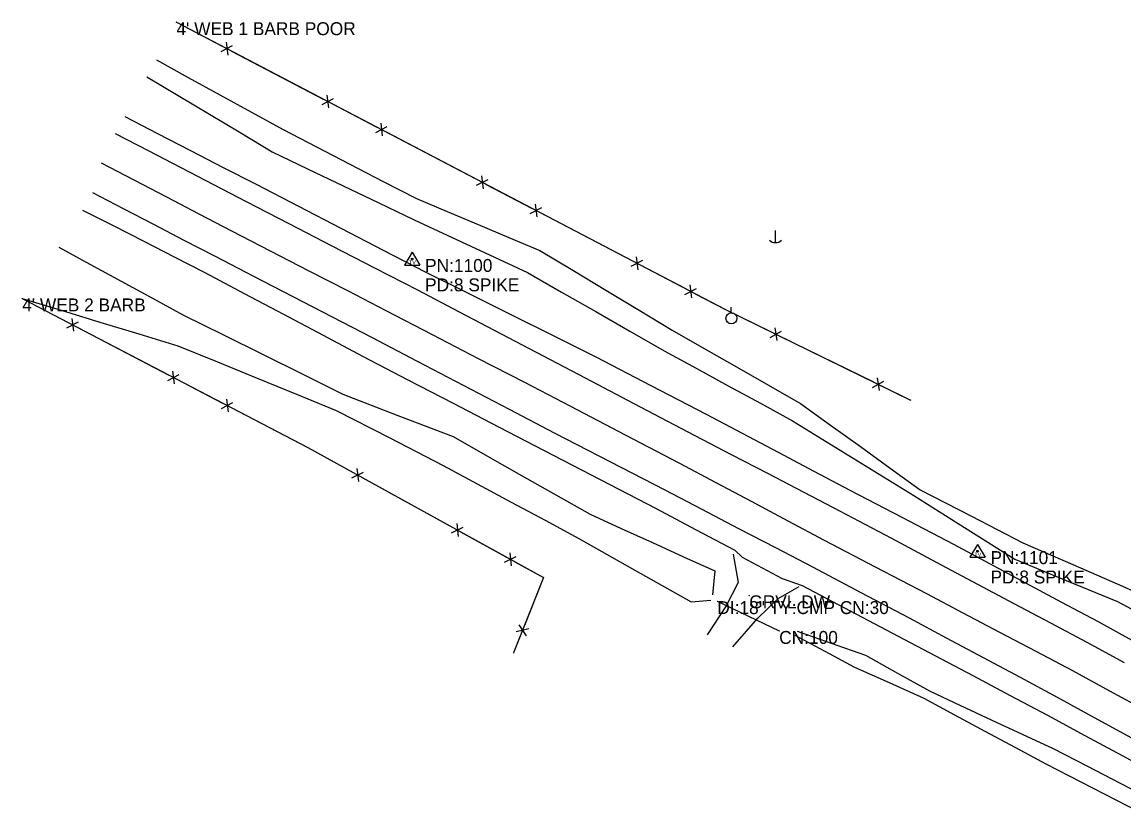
# Model space of a CAD drawing. Extents: x 1193883 to 1197064, y 1474583 to 1477379.
# Drawn here: x 1193883 to 1194308.8, y 1477071.5 to 1477379.2 of the extents above; entities that cross this region are included whole.
import ezdxf

# ---------------------------------------------------------------- set-up
doc = ezdxf.new("R2010")
doc.units = 0
for name, color, linetype in [('S_DITCHLINE', 7, 'Continuous'), ('S_DRG_PT_SYM', 7, 'Continuous'), ('S_DRIVEWAY', 7, 'Continuous'), ('S_EDGE_PAVEMENT', 7, 'Continuous'), ('S_FENCE', 7, 'Continuous'), ('S_FENCE_ANNOT', 7, 'Continuous'), ('S_MSC_PT_SYM', 7, 'Continuous'), ('S_PAVEMENT_CROWN', 7, 'Continuous'), ('S_SECONDARY_CTL', 7, 'Continuous'), ('S_SECONDARY_CTL_ANNOT', 7, 'Continuous'), ('S_SHOULDER', 7, 'Continuous'), ('S_SIDE_DRAIN', 7, 'Continuous'), ('S_SIDE_DRAIN_ANNOT', 7, 'Continuous'), ('S_SURVEY_TEXT_ANNOT', 7, 'Continuous'), ('S_UTILITY_POLE', 7, 'Continuous')]:
    doc.layers.add(name, color=color, linetype=linetype)

msp = doc.modelspace()

# ---------------------------------------------------------------- linework, layer by layer
at = {"layer": 'S_DITCHLINE'}
for points in [[(1193934.94, 1477364.5), (1193947.19, 1477357.77), (1193959.44, 1477351.04), (1193971.69, 1477344.3), (1193983.94, 1477337.57), (1193996.8, 1477330.9), (1194009.66, 1477324.23), (1194022.52, 1477317.56), (1194035.38, 1477310.89), (1194047.29, 1477305.89), (1194059.19, 1477300.89), (1194071.1, 1477295.89), (1194083.01, 1477290.89), (1194095.81, 1477283.18), (1194108.61, 1477275.46), (1194121.41, 1477267.75), (1194134.21, 1477260.03), (1194146.62, 1477252.94), (1194159.02, 1477245.84), (1194171.43, 1477238.75), (1194183.84, 1477231.66), (1194195.38, 1477223.33), (1194206.93, 1477215.01), (1194218.47, 1477206.69), (1194230.01, 1477198.36), (1194249.87, 1477188.1), (1194269.73, 1477177.84), (1194288.97, 1477169.49), (1194308.2, 1477161.14), (1194323.51, 1477154.1)], [(1193931.19, 1477357.98), (1193943.29, 1477350.74), (1193955.4, 1477343.5), (1193967.5, 1477336.26), (1193979.61, 1477329.03), (1193993.34, 1477322.44), (1194007.08, 1477315.86), (1194020.82, 1477309.28), (1194034.56, 1477302.69), (1194056.42, 1477292.52), (1194078.29, 1477282.34), (1194091.49, 1477274.78), (1194104.68, 1477267.21), (1194117.88, 1477259.65), (1194131.08, 1477252.08), (1194143.48, 1477245.32), (1194155.87, 1477238.55), (1194168.27, 1477231.79), (1194180.67, 1477225.03), (1194192.41, 1477217.8), (1194204.15, 1477210.58), (1194215.88, 1477203.35), (1194227.62, 1477196.13), (1194247.11, 1477183.81), (1194266.6, 1477171.49), (1194286.46, 1477163.33), (1194306.32, 1477155.18), (1194320.76, 1477147.45)], [(1193897.17, 1477292.11), (1193909.22, 1477285.56), (1193921.28, 1477279), (1193933.34, 1477272.44), (1193945.39, 1477265.88), (1193960.77, 1477258.25), (1193976.15, 1477250.61), (1193991.53, 1477242.98), (1194006.91, 1477235.34), (1194028.24, 1477227.11), (1194049.56, 1477218.87), (1194062.79, 1477211.37), (1194076.01, 1477203.88), (1194089.24, 1477196.38), (1194102.46, 1477188.89), (1194114.52, 1477183.41), (1194126.57, 1477177.94), (1194138.62, 1477172.46), (1194150.67, 1477166.99), (1194149.79, 1477157.71)], [(1193882.99, 1477272.33), (1193898.05, 1477267.75), (1193913.11, 1477263.18), (1193928.17, 1477258.6), (1193943.24, 1477254.02), (1193958.52, 1477247.77), (1193973.81, 1477241.52), (1193989.1, 1477235.27), (1194004.39, 1477229.03), (1194025.07, 1477218.36), (1194045.75, 1477207.7), (1194058.86, 1477200.64), (1194071.97, 1477193.59), (1194085.08, 1477186.54), (1194098.19, 1477179.49), (1194119.83, 1477167.26), (1194141.48, 1477155.03), (1194149.17, 1477155.65)], [(1194181.57, 1477142.09), (1194193.14, 1477135.96), (1194204.71, 1477129.83), (1194218.09, 1477123.79), (1194231.46, 1477117.74), (1194243.25, 1477111.4), (1194255.04, 1477105.06), (1194266.83, 1477098.71), (1194278.62, 1477092.37), (1194292.11, 1477085.41), (1194305.6, 1477078.44), (1194319.09, 1477071.47)], [(1194182.44, 1477143.74), (1194195.66, 1477139.09), (1194208.88, 1477134.44), (1194221.24, 1477127.51), (1194233.61, 1477120.58), (1194245.56, 1477115.01), (1194257.51, 1477109.43), (1194269.46, 1477103.86), (1194281.41, 1477098.29), (1194294.37, 1477091.61), (1194307.32, 1477084.93), (1194320.28, 1477078.25)]]:
    msp.add_lwpolyline(points, dxfattribs=at)
at = {"layer": 'S_DRG_PT_SYM'}
for points in [[(1194151.64, 1477155.29), (1194151.64, 1477155.34), (1194151.64, 1477155.29), (1194151.59, 1477155.29), (1194151.64, 1477155.29), (1194151.64, 1477155.24), (1194151.64, 1477155.29), (1194151.69, 1477155.29)], [(1194175.55, 1477143.76), (1194175.55, 1477143.81), (1194175.55, 1477143.76), (1194175.5, 1477143.76), (1194175.55, 1477143.76), (1194175.55, 1477143.71), (1194175.55, 1477143.76), (1194175.6, 1477143.76)]]:
    msp.add_lwpolyline(points, dxfattribs=at)
at = {"layer": 'S_DRIVEWAY'}
for points in [[(1194157.73, 1477173.42), (1194159.73, 1477162.49), (1194155.1, 1477153.51), (1194147.71, 1477142.28)], [(1194157.61, 1477137.66), (1194167.36, 1477148.7), (1194175.15, 1477156.3), (1194183.29, 1477160.93)]]:
    msp.add_lwpolyline(points, dxfattribs=at)
at = {"layer": 'S_EDGE_PAVEMENT'}
for points in [[(1193919.03, 1477336.12), (1193931.66, 1477329.53), (1193944.29, 1477322.94), (1193956.92, 1477316.35), (1193969.55, 1477309.77), (1193986.1, 1477301.24), (1194002.65, 1477292.7), (1194019.19, 1477284.17), (1194035.74, 1477275.64), (1194051.95, 1477267.13), (1194068.17, 1477258.62), (1194084.38, 1477250.11), (1194100.59, 1477241.6), (1194121.79, 1477230.46), (1194142.99, 1477219.33), (1194157.03, 1477212.03), (1194171.08, 1477204.73), (1194185.13, 1477197.43), (1194199.17, 1477190.13), (1194218.65, 1477179.7), (1194238.13, 1477169.27), (1194252.2, 1477161.83), (1194266.27, 1477154.38), (1194280.35, 1477146.93), (1194294.42, 1477139.49), (1194308.91, 1477131.54)], [(1193910.25, 1477313.24), (1193922.01, 1477307.12), (1193933.77, 1477301), (1193945.54, 1477294.88), (1193957.3, 1477288.76), (1193972.47, 1477280.89), (1193987.64, 1477273.02), (1194002.82, 1477265.15), (1194017.99, 1477257.28), (1194035.72, 1477248.01), (1194053.45, 1477238.75), (1194071.18, 1477229.48), (1194088.91, 1477220.21), (1194110.14, 1477209.24), (1194131.37, 1477198.26), (1194145.63, 1477190.84), (1194159.89, 1477183.42), (1194174.15, 1477176), (1194188.42, 1477168.58), (1194207.1, 1477158.69), (1194225.78, 1477148.79), (1194240.06, 1477141.15), (1194254.34, 1477133.51), (1194268.62, 1477125.87), (1194282.9, 1477118.23), (1194297.29, 1477110.37), (1194311.68, 1477102.51)]]:
    msp.add_lwpolyline(points, dxfattribs=at)
at = {"layer": 'S_FENCE'}
for p, q in [((1193942.65, 1477379.08), (1194154.51, 1477268.14)), ((1193959.92, 1477367.72), (1193964.36, 1477370.02)), ((1193961.82, 1477371.35), (1193962.46, 1477366.39)), ((1194000.8, 1477350.94), (1194001.44, 1477345.98)), ((1193998.9, 1477347.31), (1194003.34, 1477349.61)), ((1194019.66, 1477336.44), (1194024.1, 1477338.74)), ((1194021.56, 1477340.07), (1194022.2, 1477335.11)), ((1194058.63, 1477316.03), (1194063.07, 1477318.33)), ((1194060.53, 1477319.66), (1194061.17, 1477314.7)), ((1194081.29, 1477308.79), (1194081.93, 1477303.83)), ((1194079.39, 1477305.16), (1194083.83, 1477307.46)), ((1194118.37, 1477284.75), (1194122.81, 1477287.05)), ((1194120.27, 1477288.38), (1194120.91, 1477283.42)), ((1194139.13, 1477273.88), (1194143.57, 1477276.18)), ((1194141.03, 1477277.51), (1194141.67, 1477272.55)), ((1193883.04, 1477272.3), (1193993.41, 1477214.63)), ((1194154.51, 1477268.14), (1194226.25, 1477233.04)), ((1193900.31, 1477260.97), (1193904.74, 1477263.27)), ((1193902.2, 1477264.6), (1193902.85, 1477259.64)), ((1194172.09, 1477257.26), (1194176.46, 1477259.68)), ((1194173.89, 1477260.94), (1194174.66, 1477256)), ((1193941.18, 1477244.23), (1193941.82, 1477239.28)), ((1193939.28, 1477240.6), (1193943.72, 1477242.91)), ((1194211.61, 1477237.92), (1194215.98, 1477240.34)), ((1194213.41, 1477241.6), (1194214.18, 1477236.66)), ((1193960.03, 1477229.76), (1193964.47, 1477232.06)), ((1193961.93, 1477233.39), (1193962.57, 1477228.43)), ((1193993.41, 1477214.63), (1194084.44, 1477164.44)), ((1194012.4, 1477206.5), (1194012.94, 1477201.53)), ((1194010.42, 1477202.91), (1194014.91, 1477205.11)), ((1194050.93, 1477185.26), (1194051.46, 1477180.28)), ((1194048.95, 1477181.67), (1194053.44, 1477183.87)), ((1194069.47, 1477170.36), (1194073.96, 1477172.56)), ((1194071.45, 1477173.94), (1194071.98, 1477168.97)), ((1194084.44, 1477164.44), (1194072.91, 1477135.31)), ((1194078.78, 1477144.59), (1194073.92, 1477143.44)), ((1194074.97, 1477146.1), (1194077.73, 1477141.93))]:
    msp.add_line(p, q, dxfattribs=at)
for points in [[(1193942.65, 1477379.08), (1193960.37, 1477369.8)], [(1193963.91, 1477367.94), (1193999.34, 1477349.39)], [(1194002.39, 1477347.8), (1194020.1, 1477338.52)], [(1194023.65, 1477336.66), (1194059.08, 1477318.11)], [(1194062.12, 1477316.52), (1194079.84, 1477307.24)], [(1194083.39, 1477305.38), (1194118.82, 1477286.83)], [(1194121.86, 1477285.23), (1194139.58, 1477275.96)], [(1194143.12, 1477274.1), (1194154.51, 1477268.14)], [(1193883.04, 1477272.3), (1193900.75, 1477263.04)], [(1194154.51, 1477268.14), (1194172.48, 1477259.35)], [(1193904.3, 1477261.19), (1193939.73, 1477242.68)], [(1194176.07, 1477257.59), (1194212, 1477240.01)], [(1193942.77, 1477241.09), (1193960.48, 1477231.84)], [(1194215.08, 1477238.5), (1194226.25, 1477233.04)], [(1193964.02, 1477229.98), (1193993.41, 1477214.63)], [(1193993.41, 1477214.63), (1194010.92, 1477204.98)], [(1194014.42, 1477203.05), (1194049.44, 1477183.74)], [(1194052.45, 1477182.08), (1194069.96, 1477172.42)], [(1194073.46, 1477170.49), (1194084.44, 1477164.44)], [(1194084.44, 1477164.44), (1194077.09, 1477145.87)], [(1194075.62, 1477142.16), (1194072.91, 1477135.31)]]:
    msp.add_lwpolyline(points, dxfattribs=at)
at = {"layer": 'S_MSC_PT_SYM'}
for points in [[(1193942.65, 1477379.08), (1193942.65, 1477379.13), (1193942.65, 1477379.08), (1193942.6, 1477379.08), (1193942.65, 1477379.08), (1193942.65, 1477379.03), (1193942.65, 1477379.08), (1193942.7, 1477379.08)], [(1193883.04, 1477272.3), (1193883.04, 1477272.35), (1193883.04, 1477272.3), (1193882.99, 1477272.3), (1193883.04, 1477272.3), (1193883.04, 1477272.25), (1193883.04, 1477272.3), (1193883.09, 1477272.3)], [(1194154.51, 1477268.14), (1194154.51, 1477268.19), (1194154.51, 1477268.14), (1194154.46, 1477268.14), (1194154.51, 1477268.14), (1194154.51, 1477268.09), (1194154.51, 1477268.14), (1194154.56, 1477268.14)], [(1194226.25, 1477233.04), (1194226.25, 1477233.09), (1194226.25, 1477233.04), (1194226.2, 1477233.04), (1194226.25, 1477233.04), (1194226.25, 1477232.99), (1194226.25, 1477233.04), (1194226.3, 1477233.04)], [(1193993.41, 1477214.63), (1193993.41, 1477214.68), (1193993.41, 1477214.63), (1193993.36, 1477214.63), (1193993.41, 1477214.63), (1193993.41, 1477214.58), (1193993.41, 1477214.63), (1193993.46, 1477214.63)], [(1194084.44, 1477164.44), (1194084.44, 1477164.49), (1194084.44, 1477164.44), (1194084.39, 1477164.44), (1194084.44, 1477164.44), (1194084.44, 1477164.39), (1194084.44, 1477164.44), (1194084.49, 1477164.44)], [(1194164, 1477157.53), (1194164, 1477157.58), (1194164, 1477157.53), (1194163.95, 1477157.53), (1194164, 1477157.53), (1194164, 1477157.48), (1194164, 1477157.53), (1194164.05, 1477157.53)], [(1194072.91, 1477135.31), (1194072.91, 1477135.36), (1194072.91, 1477135.31), (1194072.86, 1477135.31), (1194072.91, 1477135.31), (1194072.91, 1477135.26), (1194072.91, 1477135.31), (1194072.96, 1477135.31)]]:
    msp.add_lwpolyline(points, dxfattribs=at)
at = {"layer": 'S_PAVEMENT_CROWN'}
msp.add_lwpolyline([(1193913.56, 1477324.73), (1193926.16, 1477318.15), (1193938.76, 1477311.57), (1193951.36, 1477304.99), (1193963.96, 1477298.41), (1193978.87, 1477290.72), (1193993.79, 1477283.03), (1194008.7, 1477275.34), (1194023.61, 1477267.65), (1194041.44, 1477258.4), (1194059.27, 1477249.15), (1194077.1, 1477239.91), (1194094.93, 1477230.66), (1194116, 1477219.63), (1194137.07, 1477208.6), (1194151.02, 1477201.17), (1194164.98, 1477193.75), (1194178.93, 1477186.32), (1194192.88, 1477178.9), (1194212.66, 1477168.57), (1194232.43, 1477158.24), (1194246.54, 1477150.8), (1194260.65, 1477143.35), (1194274.75, 1477135.91), (1194288.86, 1477128.46), (1194303.2, 1477120.65), (1194317.53, 1477112.84)], dxfattribs=at)
at = {"layer": 'S_SECONDARY_CTL'}
for p, q in [((1194033.72, 1477290.16), (1194030.71, 1477285.21)), ((1194033.72, 1477290.16), (1194036.66, 1477285.21)), ((1194030.71, 1477285.21), (1194036.66, 1477285.21)), ((1194252.2, 1477177.22), (1194249.19, 1477172.26)), ((1194252.2, 1477177.22), (1194255.14, 1477172.26)), ((1194249.19, 1477172.26), (1194255.14, 1477172.26))]:
    msp.add_line(p, q, dxfattribs=at)
for centre, radius in [((1194033.72, 1477287.55), 0.311), ((1194033.72, 1477287.55), 0.183), ((1194033.72, 1477287.55), 0.103), ((1194252.2, 1477174.61), 0.311), ((1194252.2, 1477174.61), 0.183), ((1194252.2, 1477174.61), 0.103)]:
    msp.add_circle(centre, radius, dxfattribs=at)
at = {"layer": 'S_SHOULDER'}
for points in [[(1193922.67, 1477342.57), (1193935.35, 1477336.03), (1193948.03, 1477329.5), (1193960.72, 1477322.96), (1193973.4, 1477316.42), (1193989.78, 1477307.94), (1194006.17, 1477299.47), (1194022.56, 1477290.99), (1194038.95, 1477282.52), (1194055.37, 1477274.34), (1194071.8, 1477266.15), (1194088.23, 1477257.97), (1194104.65, 1477249.79), (1194125.97, 1477238.65), (1194147.28, 1477227.52), (1194161.19, 1477220.2), (1194175.09, 1477212.89), (1194189, 1477205.57), (1194202.9, 1477198.25), (1194222.9, 1477187.78), (1194242.89, 1477177.31), (1194256.8, 1477169.86), (1194270.71, 1477162.4), (1194284.62, 1477154.95), (1194298.53, 1477147.49), (1194312.98, 1477139.51)], [(1193906.36, 1477306.48), (1193918.18, 1477300.44), (1193930, 1477294.4), (1193941.81, 1477288.36), (1193953.63, 1477282.32), (1193968.85, 1477274.24), (1193984.07, 1477266.16), (1193999.28, 1477258.08), (1194014.5, 1477250), (1194032.05, 1477240.89), (1194049.6, 1477231.77), (1194067.15, 1477222.66), (1194084.7, 1477213.55), (1194106.37, 1477202.3), (1194128.04, 1477191.06), (1194143.24, 1477183.04), (1194158.45, 1477175.02), (1194161.24, 1477172.25), (1194176.66, 1477164.01), (1194184.41, 1477161.34), (1194202.97, 1477151.54), (1194221.53, 1477141.75), (1194235.96, 1477134.12), (1194250.4, 1477126.49), (1194264.84, 1477118.86), (1194279.27, 1477111.24), (1194293.7, 1477103.41), (1194308.13, 1477095.58), (1194322.56, 1477087.76)]]:
    msp.add_lwpolyline(points, dxfattribs=at)
at = {"layer": 'S_SIDE_DRAIN'}
msp.add_line((1194151.64, 1477155.29), (1194175.55, 1477143.76), dxfattribs=at)
at = {"layer": 'S_UTILITY_POLE'}
for p, q in [((1194174.05, 1477298.59), (1194174.05, 1477293.86)), ((1194156.98, 1477266.79), (1194156.98, 1477268.89))]:
    msp.add_line(p, q, dxfattribs=at)
msp.add_circle((1194157.11, 1477264.64), 2.13, dxfattribs=at)
msp.add_arc((1194174.12, 1477297.29), 3.41, 226.3972, 313.6028, dxfattribs=at)

# ---------------------------------------------------------------- texts
at = {"layer": 'S_FENCE_ANNOT'}
for s, p in [("4' WEB 1 BARB POOR", (1193942.65, 1477374.08)), ("4' WEB 2 BARB", (1193883.04, 1477267.3))]:
    msp.add_text(s, height=5, dxfattribs=at).set_placement(p)
at = {"layer": 'S_SECONDARY_CTL'}
for p in [(1194032.51, 1477285.54), (1194250.99, 1477172.59)]:
    msp.add_text('TV', height=1.5, rotation=360, dxfattribs=at).set_placement(p)
at = {"layer": 'S_SECONDARY_CTL_ANNOT'}
for s, p in [('PN:1100', (1194038.72, 1477282.55)), ('PD:8 SPIKE', (1194038.72, 1477275.05)), ('PN:1101', (1194257.2, 1477169.61)), ('PD:8 SPIKE', (1194257.2, 1477162.11))]:
    msp.add_text(s, height=5, dxfattribs=at).set_placement(p)
at = {"layer": 'S_SIDE_DRAIN_ANNOT'}
for s, p in [('DI:18" TY:CMP CN:30', (1194151.64, 1477150.29)), ('CN:100', (1194175.55, 1477138.76))]:
    msp.add_text(s, height=5, dxfattribs=at).set_placement(p)
at = {"layer": 'S_SURVEY_TEXT_ANNOT'}
msp.add_text('GRVL DW', height=5, dxfattribs=at).set_placement((1194164, 1477152.53))

doc.saveas('drawing.dxf')
